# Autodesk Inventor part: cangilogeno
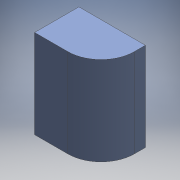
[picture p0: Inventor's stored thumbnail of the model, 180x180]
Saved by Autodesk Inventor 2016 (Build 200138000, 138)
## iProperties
Created: 2016-06
Part Number: cangilogeno
Material: Genérico
Document SubType Name: Modeling
Designer: adm
Density: 1 g/cm^3
Appearance: Valor por defecto
Author: adm
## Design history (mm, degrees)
sketch "Boceto1"
  geometry: L1 (15, 10)-(-15, 10); L2 (-15, 10)-(-15, -10); L3 (-15, -10)-(0, -10); L4 (15, 5)-(15, 10); L5 (15, 10)-(-15, -10); L6 (-15, 10)-(15, -10); A1 r 15 centre (0, 5) between (0, -10) and (15, 5); 1 further point
  constraints: 12 end point, 2 midpoint, 2 parallel, 2 point on circle, 2 point on line, 2 tangent, 1 centre point, 1 horizontal, 1 perpendicular
  dimensions: "d0" = 30 distance of L6.end L2.end; "d1" = 20 distance of L2.end L1.end; "d2" = 15 radius of A1
extrude "Extrusión1" new body sketch "Boceto1" distance "d3" = 40; taper "d4" = 0 deg
feature "Vaciado1" dims "d5" = 4
node "Sólido1"
